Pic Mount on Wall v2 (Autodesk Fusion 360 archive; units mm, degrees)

design "Pic Mount on Wall" references "Glock tool holder"
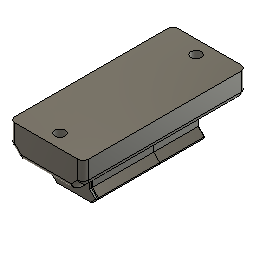
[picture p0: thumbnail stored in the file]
external_derived "ExternalDerived"
sketch "Sketch1" plane through (0, 0, 0) normal (0, 0, 1) x axis (1, 0, 0)
  line L1 (19.6871, -13.589) -> (-21.0466, -13.589)
  line L2 (19.6871, 28.5727) -> (19.6871, -13.589)
  line L3 (-21.0466, 28.5727) -> (19.6871, 28.5727)
  line L4 (-21.0466, -13.589) -> (-21.0466, 28.5727)
  horizontal L1
  perpendicular L1 L2
  perpendicular L2 L3
  perpendicular L1 L4
extrude "Extrude1" cut sketch "Sketch1" blind -183.3118 from offset 12.7
sketch "Sketch2" plane through (-7.747, 0, 0) normal (-1, 0, 0) x axis (0, 0, 1)
  line L1 (-33.241, -22.2215) -> (-28.0848, -22.2215)
  line L2 (-34.8028, -95.8564) -> (-34.8028, -5.84)
  line L3 (-171.6011, -95.8564) -> (-34.8028, -95.8564)
  line L4 (-171.6011, -5.84) -> (-171.6011, -95.8564)
  line L5 (-34.8028, -5.84) -> (-171.6011, -5.84)
  perpendicular L1 L2
  perpendicular L2 L3
  perpendicular L3 L4
  perpendicular L2 L5
extrude "Extrude2" cut sketch "Sketch2" profile of L2 L3 L4 L5 blind -36.4236 from offset 12.7
sketch "Sketch3" plane through (0, -23.3427, 0) normal (0, -1, 0) x axis (1, 0, 0)
  line L1 (10.5414, -33.7749) -> (10.5414, -2.9718)
  line L2 (13.2113, -3.4519) -> (-13.6416, -3.4519)
  line L3 (13.2113, -34.6752) -> (13.2113, -3.4519)
  line L4 (-12.6246, -34.6752) -> (13.2113, -34.6752)
  line L5 (-13.6416, -3.4519) -> (-12.6246, -34.6752)
  line L6 (-13.6416, 6.2993) -> (-13.6416, -3.4519)
  line L7 (13.2113, 6.2993) -> (-13.6416, 6.2993)
  line L8 (13.2113, -3.4519) -> (13.2113, 6.2993)
  perpendicular L1 L2
  perpendicular L2 L3
  perpendicular L3 L4
  perpendicular L2 L6
  perpendicular L6 L7
  perpendicular L2 L8
extrude "Extrude3" cut sketch "Sketch3" profile of L2 L6 L7 L8 against normal blind 15.367
delete_face "DeleteFace1"
delete_face "DeleteFace2"
extrude "Extrude1" new body of existing geometry to an object
delete_face "DeleteFace3"
delete_face "DeleteFace4"
delete_face "DeleteFace5"
delete_face "DeleteFace6"
extrude "Extrude2" new body of existing geometry blind 25.4
sketch "Sketch4" plane through (0, -13.589, 0) normal (0, 1, 0) x axis (0, 0, 1)
  line L1 (-34.8028, -9.4996) -> (-3.4519, -9.4996)
  line L2 (-34.8028, 9.2456) -> (-3.4519, 9.2456)
  line L3 (-6.2204, 9.2456) -> (-6.2204, -9.4996)
  line L4 (-60.2028, 9.2456) -> (-34.8028, 9.2456)
  line L5 (-57.0204, 9.2456) -> (-6.2204, 9.2456)
  line L6 (-60.2028, -9.4996) -> (-34.8028, -9.4996)
  line L7 (-57.0204, -9.4996) -> (-57.0204, 9.2456)
  line L8 (-57.0204, -9.4996) -> (-6.2204, -9.4996)
  line L9 (-57.0204, -13.6255) -> (-57.0204, -9.4996)
  line L10 (-6.2204, -13.6255) -> (-57.0204, -13.6255)
  line L11 (-6.2204, -9.4996) -> (-6.2204, -13.6255)
  line L12 (-6.2204, 12.6645) -> (-6.2204, 9.2456)
  line L13 (-57.0204, 12.6645) -> (-6.2204, 12.6645)
  line L14 (-57.0204, 9.2456) -> (-57.0204, 12.6645)
  line L15 (-63.1409, 12.6645) -> (-57.0204, 12.6645)
  line L16 (-63.1409, -13.6255) -> (-63.1409, 12.6645)
  line L17 (-57.0204, -13.6255) -> (-63.1409, -13.6255)
  line L18 (-1.7561, -13.6255) -> (-6.2204, -13.6255)
  line L19 (-1.7561, 12.6645) -> (-1.7561, -13.6255)
  line L20 (-6.2204, 12.6645) -> (-1.7561, 12.6645)
  point P6 (-6.2204, -9.4996)
  point P7 (-6.2204, 9.2456)
  point P10 (-57.0204, 9.2456)
  point P13 (-57.0204, -9.4996)
  coincident L1 P6
  coincident L2 P7
  perpendicular L2 L3
  coincident L4 P10
  coincident L6 P13
  perpendicular L4 L7
  perpendicular L6 L9
  perpendicular L9 L10
  perpendicular L1 L11
  perpendicular L2 L12
  perpendicular L12 L13
  perpendicular L4 L14
  perpendicular L14 L15
  perpendicular L10 L16
  perpendicular L9 L17
  perpendicular L11 L18
  perpendicular L13 L19
  perpendicular L12 L20
  dimension "d13" distance P7 P10 = 50.8
extrude "Extrude4" cut sketch "Sketch4" profile of L3 L7 L9 L11 L12 L14 L15 L16 L17 L18 L19 L20 to an object
delete_face "DeleteFace7"
delete_face "DeleteFace8"
delete_face "DeleteFace9"
delete_face "DeleteFace10"
sketch "Sketch5" plane through (0, -23.3427, 0) normal (0, -1, 0) x axis (1, 0, 0)
  line L1 (7.7216, -34.8028) -> (7.7216, -6.2204)
  line L2 (8.0268, -32.987) -> (-8.1276, -32.987)
  line L3 (8.0268, -38.3464) -> (-8.1276, -38.3464)
  line L4 (-8.1276, -42.9946) -> (-8.1276, -38.3464)
  line L5 (8.0268, -57.0204) -> (8.0268, -34.8028)
  line L6 (8.0268, -42.9946) -> (-8.1276, -42.9946)
  line L7 (-8.1276, -48.354) -> (-8.1276, -42.9946)
  line L8 (-8.1276, -53.0022) -> (-8.1276, -48.354)
  line L9 (8.0268, -53.0022) -> (-8.1276, -53.0022)
  line L10 (8.0268, -48.354) -> (-8.1276, -48.354)
  line L11 (11.6034, -48.354) -> (8.0268, -48.354)
  line L12 (11.6034, -53.0022) -> (11.6034, -48.354)
  line L13 (8.0268, -53.0022) -> (11.6034, -53.0022)
  line L14 (-12.1861, -53.0022) -> (-8.1276, -53.0022)
  line L15 (-12.1861, -48.354) -> (-12.1861, -53.0022)
  line L16 (-8.1276, -48.354) -> (-12.1861, -48.354)
  line L17 (-13.0161, -42.9946) -> (-8.1276, -42.9946)
  line L18 (-13.0161, -38.3464) -> (-13.0161, -42.9946)
  line L19 (-8.1276, -38.3464) -> (-13.0161, -38.3464)
  line L20 (11.9895, -38.3464) -> (8.0268, -38.3464)
  line L21 (11.9895, -42.9946) -> (11.9895, -38.3464)
  line L22 (8.0268, -42.9946) -> (11.9895, -42.9946)
  point P2 (-8.1276, -32.987)
  point P6 (-8.1276, -32.987)
  point P3 (8.0268, -32.987)
  point P7 (8.0268, -32.987)
  point P13 (8.0268, -42.9946)
  point P16 (8.0268, -53.0022)
  point P17 (8.0268, -48.354)
  point P8 (-8.1276, -38.3464)
  point P10 (-8.1276, -42.9946)
  point P14 (-8.1276, -48.354)
  point P15 (-8.1276, -53.0022)
  coincident P2 P6
  coincident P3 P7
  perpendicular L3 L4
  coincident L5 P13
  perpendicular L4 L6
  perpendicular L6 L7
  parallel L7 L8
  coincident L5 P16
  perpendicular L5 L9
  coincident L5 P17
  perpendicular L5 L10
  perpendicular L5 L11
  perpendicular L9 L12
  perpendicular L5 L13
  perpendicular L8 L14
  perpendicular L10 L15
  perpendicular L7 L16
  perpendicular L7 L17
  perpendicular L3 L18
  perpendicular L4 L19
  perpendicular L5 L20
  perpendicular L6 L21
  perpendicular L5 L22
  dimension "d18" = 5.3594
  dimension "d19" distance P8 P10 = 4.6482
  dimension "d20" distance P10 P14 = 5.3594
  dimension "d21" distance P14 P15 = 4.6482
extrude "Extrude4" cut sketch "Sketch5" profile of L3 L4 L5 L6 L8 L9 L10 L11 L12 L13 L14 L15 L16 L17 L18 L19 L20 L21 L22 to an object
extrude "Extrude5" add of existing geometry blind 0.9525
extrude "Extrude6" cut of existing geometry blind -0.9525
sketch "Sketch6" plane through (0, 0, -5.2679) normal (0, 0, 1) x axis (1, 0, 0)
  line L1 (-7.9756, -13.2961) -> (-7.9756, -15.113)
  line L2 (-9.9762, -13.2961) -> (-7.9756, -13.2961)
  line L3 (-7.9756, -15.113) -> (-9.9762, -13.2961)
  line L4 (-9.4996, -13.589) -> (9.2456, -13.589)
  line L5 (7.7216, -13.2961) -> (7.7216, -15.113)
  line L6 (9.8346, -13.2961) -> (7.7216, -13.2961)
  line L7 (7.7216, -15.113) -> (9.8346, -13.2961)
  arc A1 centre (-9.4996, -15.113) radius 1.524 clockwise from (-9.4996, -13.589) to (-7.9756, -15.113)
  point P2 (-7.9756, -15.113)
  point P6 (-7.9756, -15.113)
  point P9 (-7.9756, -15.113)
  point P10 (-7.9756, -15.113)
  point P11 (7.7216, -15.113)
  point P14 (7.7216, -15.113)
  point P17 (7.7216, -15.113)
  point P18 (7.7216, -15.113)
  coincident P2 P6
  tangent A1 L1
  vertical L1
  perpendicular L1 L2
  coincident P9 P10
  coincident P11 P14
  perpendicular L4 L5
  perpendicular L5 L6
  coincident P17 P18
extrude "Extrude5" cut sketch "Sketch6" to an object
sketch "Sketch7" plane through (0, 0, -56.0679) normal (0, 0, -1) x axis (-1, 0, 0)
  line L1 (-7.7216, -13.589) -> (7.9756, -13.589)
  line L2 (7.9756, -13.589) -> (-7.7216, -13.589)
  line L3 (0.127, 5.334) -> (0.127, -13.589)
  line L4 (3.429, 5.334) -> (3.429, -13.589)
  line L5 (-3.175, 5.7663) -> (-3.175, -13.589)
  line L6 (-13.4313, 18.0107) -> (-17.5962, 18.0107)
  line L7 (17.8616, 18.161) -> (14.1667, 18.161)
  line L8 (12.827, -13.589) -> (3.429, -13.589)
  line L9 (-12.573, -0.889) -> (-12.573, -9.779)
  line L10 (12.827, -0.889) -> (12.827, -9.779)
  line L11 (0.127, -13.589) -> (9.017, -13.589)
  line L12 (-8.763, -13.589) -> (-3.175, -13.589)
  arc A1 centre (0.127, 18.161) radius 12.827 clockwise from (12.9018, 17.0054) to (-12.6711, 17.2999)
  arc A2 centre (0.127, 18.161) radius 19.05 clockwise from (-15.113, 6.731) to (-18.8621, 16.6393)
  arc A3 centre (0.127, 18.161) radius 19.05 clockwise from (19.1283, 16.8003) to (15.367, 6.731)
  arc A4 centre (-17.5962, 16.7407) radius 1.27 clockwise from (-18.8621, 16.6393) to (-17.5962, 18.0107)
  arc A5 centre (-13.4313, 17.2487) radius 0.762 clockwise from (-13.4313, 18.0107) to (-12.6711, 17.2999)
  arc A6 centre (14.1667, 16.891) radius 1.27 clockwise from (12.9018, 17.0054) to (14.1667, 18.161)
  arc A7 centre (17.8616, 16.891) radius 1.27 clockwise from (17.8616, 18.161) to (19.1283, 16.8003)
  arc A8 centre (-25.273, -0.889) radius 12.7 clockwise from (-15.113, 6.731) to (-12.573, -0.889)
  arc A9 centre (25.527, -0.889) radius 12.7 clockwise from (12.827, -0.889) to (15.367, 6.731)
  arc A10 centre (-8.763, -9.779) radius 3.81 clockwise from (-8.763, -13.589) to (-12.573, -9.779)
  arc A11 centre (9.017, -9.779) radius 3.81 clockwise from (12.827, -9.779) to (9.017, -13.589)
  point P6 (0.127, -13.589)
  point P12 (-3.175, 5.7663)
  point P13 (0.127, 5.334)
  point P28 (-12.573, -13.589)
  point P27 (12.827, -13.589)
  point P7 (0.127, 18.161)
  midpoint L1 P6
  perpendicular L2 L3
  concentric A1 A2
  horizontal L6
  perpendicular L4 L7
  parallel L3 L5
  coincident A1 P12
  coincident A1 P13
  tangent L6 A4
  tangent A2 A4
  tangent L6 A5
  tangent A1 A5
  tangent L7 A6
  tangent A1 A6
  tangent L7 A7
  tangent A3 A7
  perpendicular L3 L8
  perpendicular L9 L11
  perpendicular L8 L10
  collinear L11 L12
  tangent L9 A8
  tangent A2 A8
  tangent L10 A9
  tangent A3 A9
  coincident P28 L9
  coincident P28 L12
  tangent L9 A10
  tangent L12 A10
  coincident P27 L11
  coincident P27 L10
  tangent L11 A11
  tangent L10 A11
  dimension "d32" distance P6 P7 = 31.75
  dimension "d33" diameter A1 = 25.654
  dimension "d34" diameter A2 = 38.1
  dimension "d35" = 3.302
  dimension "d39" radius A4 = 1.27
  dimension "d40" radius A5 = 0.762
  dimension "d41" radius A6 = 1.27
  dimension "d42" radius A7 = 1.27
  dimension "d47" distance P6 P27 = 12.7
  dimension "d48" distance P27 P28 = 25.4
  dimension "d49" radius A8 = 12.7
  dimension "d50" radius A9 = 12.7
  dimension "d51" radius A10 = 3.81
  dimension "d52" radius A11 = 3.81
extrude "Extrude9" add sketch "Sketch7" profile of L1 L2 L3 A1 A3 L5 L6 L7 A4 A5 A6 A7 L8 L12 L9 L10 A8 A9 A10 A11 to an object
extrude "Extrude8" add sketch "Sketch7" profile of L1 L2 L3 A1 A3 L5 L6 L7 A4 A5 A6 A7 to an object
sketch "Sketch9" plane through (12.573, 0, 0) normal (1, 0, 0) x axis (0, 0, -1)
  line L1 (5.2679, -9.779) -> (56.0679, -9.779)
  line L2 (5.2679, 18.161) -> (56.0679, 18.161)
  line L3 (30.6679, 20.657) -> (30.6679, -9.779)
  line L4 (14.7929, 20.657) -> (14.7929, 18.161)
  line L5 (-2.5282, -9.779) -> (14.7929, -9.779)
  line L6 (-2.5282, 21.9055) -> (-2.5282, -9.779)
  line L7 (30.6679, 21.9055) -> (-2.5282, 21.9055)
  line L8 (30.6679, 20.657) -> (30.6679, 21.9055)
  arc A1 centre (14.7929, 6.096) radius 15.8886 clockwise from (30.6679, 6.753) to (14.1359, -9.779)
  point P6 (30.6679, -9.779)
  point P14 (30.6679, 6.753)
  point P15 (14.1359, -9.779)
  point P16 (14.7929, 18.161)
  point P8 (14.7929, -9.779)
  point P10 (14.7929, 6.096)
  midpoint L1 P6
  perpendicular L2 L3
  perpendicular L5 L6
  perpendicular L6 L7
  perpendicular L7 L8
  coincident L3 P14
  coincident L1 P15
  parallel L3 L4
  coincident L2 P16
  dimension "d59" distance P8 P10 = 15.875
extrude "Extrude11" cut sketch "Sketch9" profile of L1 L3 A1 L5 L6 L7 L8 blind -47.752 from offset 12.7
sketch "Sketch10" plane through (0, 0, -56.0679) normal (0, 0, -1) x axis (-1, 0, 0)
  line L1 (-0.0207, -5.3331) -> (-0.0207, 5.3349)
  line L2 (5.8213, -5.3331) -> (-0.0207, -5.3331)
  line L3 (-0.0207, -5.3331) -> (5.8213, -5.3331)
  line L4 (-5.8627, -5.3331) -> (-0.0207, -5.3331)
  line L5 (-5.8627, -0.7611) -> (-5.8627, -5.3331)
  line L6 (5.8213, -0.7611) -> (5.8213, -5.3331)
  line L7 (-3.3227, -0.7611) -> (-3.3227, 5.8066)
  line L8 (3.2813, -0.7611) -> (3.2813, 5.7279)
  line L9 (-3.3227, -0.7611) -> (-5.8627, -0.7611)
  line L10 (3.2813, -0.7611) -> (5.8213, -0.7611)
  line L11 (-3.3227, 6.7705) -> (-3.3227, 5.8066)
  line L12 (3.2813, 6.7705) -> (-3.3227, 6.7705)
  line L13 (3.2813, 5.7279) -> (3.2813, 6.7705)
  arc A1 centre (0.127, 18.161) radius 12.827 clockwise from (12.9018, 17.0054) to (-12.6711, 17.2999)
  point P5 (-0.0207, 5.3349)
  point P13 (-3.3227, 5.8066)
  point P14 (3.2813, 5.7279)
  point P6 (-0.0207, -5.3331)
  point P8 (-5.8627, -5.3331)
  midpoint A1 P5
  vertical L1
  perpendicular L1 L2
  perpendicular L1 L4
  perpendicular L4 L5
  perpendicular L2 L6
  perpendicular L7 L9
  perpendicular L8 L10
  parallel L1 L7
  coincident A1 P13
  parallel L1 L8
  coincident A1 P14
  parallel L7 L11
  perpendicular L8 L12
  dimension "d65" distance P6 P8 = 5.842
extrude "Extrude12" cut sketch "Sketch10" against normal blind 18.288
sketch "Sketch11" plane through (0, -5.3331, 0) normal (0, 1, 0) x axis (-1, 0, 0)
  line L1 (-5.8627, -56.0679) -> (5.8213, -56.0679)
  line L2 (-8.0268, -56.0679) -> (8.1276, -56.0679)
  line L3 (0.0504, -56.0679) -> (-0.0207, -56.0679)
  line L4 (-3.3227, -37.7799) -> (-3.3227, -56.0679)
  line L5 (-5.8627, -37.7799) -> (5.8213, -37.7799)
  line L6 (3.2813, -37.7799) -> (3.2813, -43.3679)
  line L7 (3.2813, -37.7799) -> (-3.3227, -37.7799)
  line L8 (-3.3227, -43.3679) -> (-3.3227, -37.7799)
  arc A1 centre (-0.0207, -43.3679) radius 3.302 clockwise from (-3.3227, -43.3679) to (3.2813, -43.3679)
  point P6 (-0.0207, -56.0679)
  point P7 (0.0504, -56.0679)
  point P11 (3.2813, -37.7799)
  point P15 (3.2813, -37.7799)
  point P10 (-3.3227, -37.7799)
  point P16 (-3.3227, -37.7799)
  point P17 (3.2813, -37.7799)
  point P18 (-3.3227, -43.3679)
  point P8 (-0.0207, -43.3679)
  midpoint L1 P6
  midpoint L2 P7
  tangent L4 A1
  coincident P11 P15
  perpendicular L5 L6
  coincident P10 P16
  coincident P11 P17
  coincident L4 P18
  dimension "d72" distance P6 P8 = 12.7
extrude "Extrude13" add sketch "Sketch11" profile of A1 L4 L5 L6 L7 L8 blind 7.9756 from offset 4.572
sketch "Sketch12" plane through (0, 0, -37.7799) normal (0, 0, 1) x axis (1, 0, 0)
  line L1 (-3.2813, 7.2145) -> (-3.2813, 5.7279)
  line L2 (-3.2813, 7.2145) -> (-3.2813, 5.7279)
  line L3 (-3.2813, 7.2145) -> (3.3227, 7.2145)
  line L4 (3.3227, 5.8066) -> (3.3227, 7.2145)
  arc A1 centre (-0.127, 18.161) radius 12.827 clockwise from (3.3227, 5.8066) to (-3.2813, 5.7279)
  point P2 (-3.2813, 5.7279)
  point P6 (-3.2813, 5.7279)
  point P3 (-3.2813, 7.2145)
  point P7 (-3.2813, 7.2145)
  point P8 (3.3227, 7.2145)
  point P9 (3.3227, 7.2145)
  point P10 (-3.2813, 7.2145)
  point P11 (3.3227, 5.8066)
  point P12 (3.3227, 5.8066)
  point P13 (-3.2813, 5.7279)
  coincident P2 P6
  coincident P3 P7
  coincident P8 P9
  coincident P3 P10
  coincident P11 P12
  coincident P2 P13
extrude "Extrude14" cut sketch "Sketch12" against normal blind 6.5278
sketch "Sketch13" plane through (0, -9.779, 0) normal (0, 1, 0) x axis (0, 0, 1)
  line L1 (-15.4499, 15.6111) -> (-15.4499, 12.573)
  line L2 (-3.1431, 15.6111) -> (-15.4499, 15.6111)
  line L3 (-3.1431, 7.5536) -> (-3.1431, 15.6111)
  line L4 (-3.1431, 7.7216) -> (-5.2679, 7.7216)
  line L5 (-5.2679, -12.827) -> (-5.2679, 12.573)
  line L6 (-3.1431, -7.9756) -> (-5.2679, -7.9756)
  line L7 (-3.1431, -15.2405) -> (-3.1431, -7.9756)
  line L8 (-15.4499, -15.2405) -> (-3.1431, -15.2405)
  line L9 (-15.4499, -15.2405) -> (-15.4499, -12.827)
  line L10 (-6.5379, -7.9756) -> (-5.2679, -7.9756)
  line L11 (-6.5379, -7.9756) -> (-15.4499, -12.827)
  line L12 (-6.5379, 7.7216) -> (-5.2679, 7.7216)
  line L13 (-15.4499, 12.573) -> (-6.5379, 7.7216)
  point P4 (-5.2679, -7.9756)
  point P6 (-5.2679, -7.9756)
  point P3 (-5.2679, 7.7216)
  point P8 (-5.2679, 7.7216)
  point P7 (-15.4499, 12.573)
  point P9 (-15.4499, 12.573)
  point P13 (-3.1431, 7.7216)
  point P16 (-5.2679, -7.9756)
  point P5 (-15.4499, -12.827)
  point P20 (-15.4499, -12.827)
  point P22 (-15.4499, -12.827)
  point P23 (-5.2679, 7.7216)
  point P25 (-15.4499, 12.573)
  point P21 (-6.5379, -7.9756)
  point P24 (-6.5379, 7.7216)
  coincident P4 P6
  coincident P3 P8
  coincident P7 P9
  perpendicular L1 L2
  perpendicular L2 L3
  coincident L3 P13
  perpendicular L3 L4
  coincident P4 P16
  perpendicular L5 L6
  perpendicular L4 L7
  perpendicular L7 L8
  coincident P5 P20
  perpendicular L8 L9
  parallel L6 L10
  coincident P5 P22
  coincident P3 P23
  perpendicular L5 L12
  coincident P7 P25
  dimension "d80" distance P6 P21 = 1.27
  dimension "d81" distance P23 P24 = 1.27
extrude "Extrude15" cut sketch "Sketch13" profile of L1 L2 L3 L4 L6 L7 L8 L9 against normal blind 6.6802
chamfer "Chamfer1" distance 0.9144
fillet "Fillet1" radius 1.27 1.27
chamfer "Chamfer2" distance 0.6858
fillet "Fillet2" radius 1.27 1.27 1.27 1.27 1.27
chamfer "Chamfer3" distance 0.508
sketch "Sketch1" plane through (0, 0, -56.0679) normal (0, 0, -1) x axis (-1, 0, 0)
  line L1 (7.9756, -10.4648) -> (12.7648, -10.4648)
  line L2 (12.827, -9.779) -> (-12.573, -9.779)
  line L3 (12.827, 2.921) -> (12.827, -9.779)
  line L4 (-12.573, 2.921) -> (-12.573, -9.779)
  line L5 (-25.273, 2.921) -> (-12.573, 2.921)
  line L6 (-25.273, 15.621) -> (-25.273, 2.921)
  line L7 (25.527, 2.921) -> (12.827, 2.921)
  line L8 (25.527, 15.621) -> (25.527, 2.921)
  line L9 (-25.273, 15.621) -> (25.527, 15.621)
  line L10 (-28.6214, 22.1363) -> (-12.573, -9.779)
  line L11 (-28.6214, 22.1363) -> (28.7124, 22.1363)
  line L12 (12.827, -8.1595) -> (12.827, -9.779)
  line L13 (12.827, -9.779) -> (28.7124, 22.1363)
  point P2 (-12.573, -9.779)
  point P6 (-12.573, -9.779)
  point P3 (12.827, -9.779)
  point P7 (12.827, -9.779)
  point P14 (-12.573, -9.779)
  point P17 (12.827, -9.779)
  point P18 (12.827, -8.1595)
  point P8 (12.827, 2.921)
  point P9 (-12.573, 2.921)
  point P10 (-25.273, 2.921)
  point P11 (-25.273, 15.621)
  point P12 (25.527, 2.921)
  point P13 (25.527, 15.621)
  coincident P2 P6
  coincident P3 P7
  perpendicular L2 L4
  perpendicular L4 L5
  perpendicular L5 L6
  perpendicular L3 L7
  perpendicular L7 L8
  coincident P2 P14
  perpendicular L8 L11
  coincident P3 P17
  coincident L3 P18
  perpendicular L2 L12
  dimension "d93" angle L2 L3 = 90
  dimension "d94" distance P7 P8 = 12.7
  dimension "d95" distance P6 P9 = 12.7
  dimension "d96" distance P9 P10 = 12.7
  dimension "d97" distance P10 P11 = 12.7
  dimension "d98" distance P8 P12 = 12.7
  dimension "d99" distance P12 P13 = 12.7
extrude "Extrude16" cut sketch "Sketch1" profile of L2 L3 L4 L5 L6 L7 L9 L10 L11 L12 L13 to an object
sketch "Sketch2" plane through (0, 0, -56.0679) normal (0, 0, -1) x axis (-1, 0, 0)
  line L1 (-17.0631, -5.2889) -> (-12.573, -9.779)
  line L2 (-6.223, -9.779) -> (-12.573, -9.779)
  line L3 (17.3171, -5.2889) -> (12.827, -9.779)
  line L4 (19.177, -9.779) -> (12.827, -9.779)
  line L5 (-17.0631, 4.2361) -> (-17.0631, -5.2889)
  line L6 (17.3171, 4.2361) -> (17.3171, -5.2889)
  line L7 (17.3171, 4.2361) -> (-17.0631, 4.2361)
  line L8 (12.827, -9.779) -> (-12.573, -9.779)
  point P2 (-12.573, -9.779)
  point P3 (-12.573, -9.779)
  point P6 (12.827, -9.779)
  point P7 (12.827, -9.779)
  point P4 (-17.0631, -5.2889)
  point P8 (17.3171, -5.2889)
  point P10 (-17.0631, 4.2361)
  point P11 (17.3171, 4.2361)
  horizontal L2
  coincident P2 P3
  horizontal L4
  coincident P6 P7
  vertical L5
  perpendicular L4 L6
  dimension "d102" angle L1 L2 = 135
  dimension "d103" distance P3 P4 = 6.35
  dimension "d104" distance P7 P8 = 6.35
  dimension "d105" angle L3 L4 = 45
  dimension "d106" distance P4 P10 = 9.525
  dimension "d107" distance P8 P11 = 9.525
extrude "Extrude17" add sketch "Sketch2" profile of L1 L3 L5 L6 L7 L8 blind -76.2 from offset 12.7
delete_face "DeleteFace1"
delete_face "DeleteFace2"
sketch "Sketch3" plane through (0, 0, 7.4321) normal (0, 0, 1) x axis (1, 0, 0)
  line L1 (-12.1412, -9.779) -> (-7.2898, -9.779)
  line L2 (-7.9756, -5.6381) -> (-7.9756, -17.6028)
  line L3 (-15.1775, -9.779) -> (-7.9756, -9.779)
  line L4 (-7.9756, -17.6028) -> (-15.1775, -9.779)
  line L5 (7.0358, -9.779) -> (11.8872, -9.779)
  line L6 (7.7216, -6.9128) -> (7.7216, -17.4495)
  line L7 (14.6355, -9.779) -> (7.7216, -9.779)
  line L8 (7.7216, -17.4495) -> (14.6355, -9.779)
  point P2 (-7.9756, -17.6028)
  point P5 (-7.9756, -17.6028)
  point P7 (-7.9756, -9.779)
  point P9 (7.7216, -17.4495)
  point P12 (7.7216, -17.4495)
  point P14 (7.7216, -9.779)
  point P16 (7.7216, -17.4495)
  coincident P2 P5
  perpendicular L1 L2
  coincident L1 P7
  coincident L2 P7
  perpendicular L2 L3
  coincident P9 P12
  perpendicular L5 L6
  coincident L6 P14
  coincident L5 P14
  perpendicular L6 L7
  coincident P9 P16
extrude "Extrude18" cut sketch "Sketch3" to an object
delete_face "DeleteFace3"
delete_face "DeleteFace4"
sketch "Sketch4" plane through (0, -9.779, 0) normal (0, -1, 0) x axis (0, 0, -1)
  line L1 (-7.4321, -17.3171) -> (-7.4321, 17.0631)
  line L2 (68.7679, -17.3171) -> (68.7679, 17.0631)
  line L3 (62.4179, -0.127) -> (68.7679, -0.127)
  line L4 (-1.0821, -0.127) -> (-7.4321, -0.127)
  point P6 (-7.4321, -0.127)
  point P7 (68.7679, -0.127)
  point P8 (62.4179, -0.127)
  point P9 (-1.0821, -0.127)
  midpoint L1 P6
  midpoint L2 P7
  perpendicular L1 L4
  dimension "d113" distance P7 P8 = 6.35
  dimension "d114" distance P6 P9 = 6.35
hole "Hole1" HoleDepth 15.24 HoleDiameter 4.7625 TipAngle 118 CSDiameter 9.525 CSAngle 82
hole "Hole2" HoleDepth 15.24 HoleDiameter 4.7752 TipAngle 118 CSDiameter 9.525 CSAngle 82
sketch "Sketch5" plane through (-17.3171, 0, 0) normal (-1, 0, 0) x axis (0, 0, 1)
  line L1 (-68.7679, 4.2361) -> (-68.7679, -5.2889)
  line L2 (-56.0679, -0.5264) -> (-68.7679, -0.5264)
  line L3 (7.4321, 4.2361) -> (7.4321, -5.2889)
  line L4 (7.4321, -5.2889) -> (7.4321, 4.2361)
  line L5 (5.4199, -0.5264) -> (7.4321, -0.5264)
  point P4 (-68.7679, -0.5264)
  point P10 (7.4321, -0.5264)
  point P5 (-56.0679, -0.5264)
  midpoint L1 P4
  perpendicular L1 L2
  midpoint L3 P10
  perpendicular L4 L5
  dimension "d125" distance P4 P5 = 12.7
sketch "Sketch6" plane through (17.0631, 0, 0) normal (1, 0, 0) x axis (0, 0, -1)
  line L1 (5.2679, -0.5264) -> (-7.4321, -0.5264)
  line L2 (56.0679, -0.5264) -> (68.7679, -0.5264)
  line L3 (56.0679, -0.5264) -> (68.7679, -0.5264)
  point P2 (-7.4321, -0.5264)
  point P3 (-7.4321, -0.5264)
  point P5 (68.7679, -0.5264)
  point P8 (68.7679, -0.5264)
  point P4 (5.2679, -0.5264)
  point P9 (56.0679, -0.5264)
  coincident P2 P3
  coincident P5 P8
  parallel L2 L3
  dimension "d137" distance P3 P4 = 12.7
  dimension "d138" distance P8 P9 = 12.7
sketch "Sketch7" plane through (-17.3171, 0, 0) normal (-1, 0, 0) x axis (0, 0, 1)
  line L1 (7.4321, -5.2889) -> (7.4321, 4.2361)
  line L2 (-5.2679, -0.5264) -> (7.4321, -0.5264)
  point P2 (7.4321, -0.5264)
  point P5 (7.4321, -0.5264)
  point P6 (-5.2679, -0.5264)
  coincident P2 P5
  perpendicular L1 L2
  dimension "d144" distance P5 P6 = 12.7
fillet "Fillet3" radius 2.54
chamfer "Chamfer4" distance 0.508
chamfer "Chamfer5" distance 0.508
fillet "Fillet5" radius 2.54
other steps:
derived_base_feature "Derived Base Feature" bodies "Body23"
chamfer "Chamfer1" distance 0.508
extrude "Extrude3" cut sketch "Sketch4" profile of L3 L7 L9 L11 L12 L14 L15 L16 L17 L18 L19 L20 to an object
extrude "Extrude7" cut sketch "Sketch6" to an object
create_component "CreateComponent1"
named bodies: "Body23"

design "Glock tool holder"
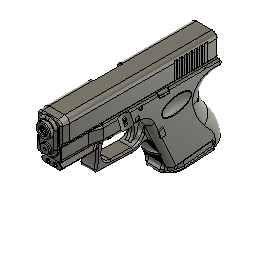
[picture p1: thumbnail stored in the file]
